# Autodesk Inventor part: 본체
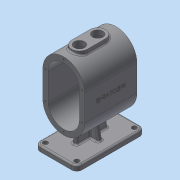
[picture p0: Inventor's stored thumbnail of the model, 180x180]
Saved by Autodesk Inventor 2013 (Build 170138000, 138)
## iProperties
Created: 2016-12
Part Number: 본체
Material: 알루미늄 6061
Document SubType Name: Modeling
Designer: mduedu
Density: 1 g/cm^3
Mass: 432.112 g
Surface Area: 1014.94 cm^2
Volume: 432.112 cm^3
Author: mduedu
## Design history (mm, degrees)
sketch "스케치1"
  geometry: L1 (40, -25)-(40, 25); L2 (-40, 25)-(-40, -25); L3 (-40, -25)-(40, 25); L4 (40, -25)-(-40, 25); L5 (0, 25)-(0, -25); A1 r 40 centre (0, 25) between (40, 25) and (-40, 25); A2 r 40 centre (0, -25) between (-40, -25) and (40, -25); 1 further point
  constraints: 10 end point, 4 point on circle, 3 tangent, 2 centre point, 2 midpoint, 2 parallel, 1 vertical
  dimensions: "d0" = 130 dimension on A2 A1; "d2" = 80 distance between parallel lines of L1 L2
extrude "돌출1" new body sketch "스케치1" stored distance "d3" = 100; taper "d4" = 0 deg
feature "쉘1" dims "d5" = 10
sketch "스케치2"
  geometry: L1 (-90, 65)-(-100, 65); L2 (-100, 65)-(-100, -65); L3 (-100, -65)-(-90, -65); L4 (-90, -65)-(-90, 65); 2 further points
  constraints: 8 end point, 2 parallel, 1 horizontal, 1 horizontal alignment, 1 midpoint, 1 perpendicular
  dimensions: "d6" = 100 distance from line of L2 point (0, 0); "d7" = 130 distance of L1.end L2.end; "d8" = 10 distance of L2.end L3.end
extrude "돌출2" join sketch "스케치2" stored distance "d9" = 80; taper "d10" = 0 deg
fillet "모깎기1" dims "d11" = 10
sketch "스케치3"
  geometry: L1 (-10, 10)-(-10, 120) reference; L2 (60, 0)-(0, 0) reference; L3 (70, 120)-(70, 10) reference; L4 (0, 130)-(60, 130) reference; A1 r 10 centre (0, 120) between (0, 130) and (-10, 120) reference; A2 r 10 centre (0, 10) between (-10, 10) and (0, 0) reference; A3 r 10 centre (60, 10) between (60, 0) and (70, 10) reference; A4 r 10 centre (60, 120) between (70, 120) and (60, 130) reference; 5 further points
  constraints: 4 coincident
hole "구멍1" sketch "스케치3" at (60, 120), (60, 10), (0, 10), (0, 120) diameter "d12" = 9; stored, may be unused: countersink angle "d16" = 90 deg, drill point angle "d18" = 118 deg; dims "d13" = 6, "d14" = 4, "d15" = 2, "d17" = 8
sketch "스케치5"
  geometry: L1 (34, 35)-(26, 35); L2 (26, 35)-(26, 95); L3 (26, 95)-(34, 95); L4 (34, 95)-(34, 35); L5 (34, 35)-(26, 95); L6 (26, 35)-(34, 95); 1 further point
  constraints: 12 end point, 2 midpoint, 2 parallel, 1 horizontal, 1 perpendicular
  dimensions: "d22" = 8 distance of L2.end L3.end; "d24" = 60 distance of L1.end L2.end
extrude "돌출3" join sketch "스케치5" stored distance "d25" = 80; taper "d26" = 0 deg
feature "면 기울기1" dims angle "d27" = 5 deg
sketch "스케치6"
  geometry: L1 (-30, -90)-(30, -90) reference; L2 (-15.072, -62.052)-(-20, -90); A1 r 40 centre (0, -25) between (-40, -25) and (40, -25) reference; 1 further point
  constraints: 2 end point, 1 point on circle, 1 point on line
  dimensions: "d28" = 20 horizontal distance of A1.centre L2.end; "d29" = 80 deg angle of L2 L1
feature "리브1" sketch "스케치6" dims "d30" = 1, "d31" = 8, "d32" = 0, "d33" = 0, "d34" = 1, "d35" = 1
fillet "모깎기2" dims "d36" = 3
fillet "모깎기3" dims "d37" = 3, "d38" = 3
node "작업 평면1"
sketch "스케치9"
  geometry: 1 further point
sketch "스케치7"
  geometry: L1 (40, 50)-(-40, 50) reference; C1 r 15 at (0, 20); 1 further point
  constraints: 1 centre point, 1 vertical alignment
  dimensions: "d40" = 30 diameter of C1; "d41" = 30 distance from line of C1.centre L1
extrude "돌출4" join sketch "스케치7" stored distance "d42" = 80; taper "d43" = 0 deg
sketch "스케치15"
  geometry: C1 r 15 at (0, -15); C2 r 15 at (0, 20) reference; 1 further point
  constraints: 1 centre point, 1 vertical alignment
  dimensions: "d83" = 30 diameter of C1; "d84" = 35 distance of C1.centre C2.centre
extrude "돌출6" join sketch "스케치15" stored distance "d85" = 10; taper "d86" = 0 deg
hole "구멍2" diameter "d46" = 20; stored, may be unused: countersink angle "d50" = 90 deg, drill point angle "d52" = 118 deg; dims "d44" = 10, "d45" = 10, "d47" = 6, "d48" = 4, "d49" = 2, "d51" = 8
hole "구멍6" diameter "d89" = 20; stored, may be unused: countersink angle "d93" = 90 deg, drill point angle "d95" = 118 deg; dims "d87" = 10, "d88" = 10, "d90" = 6, "d91" = 4, "d92" = 2, "d94" = 8
node "작업 평면2"
sketch "스케치8"
  geometry: C1 r 15 at (0, 0) reference; C2 r 15 at (0, 0); 1 further point
  constraints: 1 centre point, 1 coincident
  dimensions: "d55" = 30 diameter of C2
extrude "돌출5" cut sketch "스케치8" stored distance "d56" = 80; taper "d57" = 0 deg
sketch "스케치16"
  geometry: C1 r 15 at (0, 35); 2 further points
  constraints: 1 centre point, 1 coincident, 1 vertical alignment
  dimensions: "d96" = 30 diameter of C1
extrude "돌출7" cut sketch "스케치16" stored distance "d97" = 10; taper "d98" = 0 deg
sketch "스케치17"
  geometry: L1 (15, 0)-(15, -35); L2 (-15, 0)-(-15, -35); C1 r 10 at (0, 0) reference; C2 r 10 at (0, -35) reference; A1 r 15 centre (0, 0) between (15, 0) and (-15, 0) reference; A2 r 15 centre (0, -35) between (15, -35) and (-15, -35) reference; 1 further point
  constraints: 4 end point, 4 point on circle, 3 tangent, 1 vertical
extrude "돌출8" join sketch "스케치17" stored distance "d99" = 10; taper "d100" = 0 deg
fillet "모깎기5" dims "d101" = 3
chamfer "모따기1" distance "d58" = 1; stored, may be unused: second distance "d59" = 2, angle "d60" = 45 deg
sketch "스케치10"
  geometry: 2 further points
  constraints: 1 coincident, 1 other
feature "엠보싱1" sketch "스케치10" dims "d0" = 130, "d2" = 80, "d11" = 10, "d61" = 0.5, "d62" = 0
sketch "스케치11"
  geometry: 1 further point
hole "구멍3" sketch "스케치11" at (0, 60) diameter "d63" = 3.242; stored, may be unused: countersink angle "d67" = 90 deg, drill point angle "d69" = 120 deg; dims "d64" = 8.6, "d65" = 4, "d66" = 2, "d68" = 10.6
sketch "스케치12"
  geometry: 1 further point
hole "구멍5" sketch "스케치12" at (0, 60) diameter "d70" = 3.242; stored, may be unused: countersink angle "d74" = 90 deg, drill point angle "d76" = 120 deg; dims "d71" = 8.6, "d72" = 4, "d73" = 2, "d75" = 10.6
node "솔리드1"
mirror "대칭1"
pattern_linear "직사각형 패턴1"
pattern_linear "직사각형 패턴2"
node "투영된 루프1"
sketch "스케치13"
  geometry: L1 (-40, 25)-(-40, -25) reference; L2 (40, -25)-(40, 25) reference; L3 (35, 25)-(35, -25); L4 (-35, -25)-(-35, 25); A1 r 40 centre (0, 25) between (40, 25) and (-40, 25) reference; A2 r 40 centre (0, -25) between (-40, -25) and (40, -25) reference; A3 r 35 centre (0, 25) between (35, 25) and (-35, 25); A4 r 35 centre (0, -25) between (-35, -25) and (35, -25); 2 further points
  constraints: 5 point on circle, 4 end point, 2 centre point, 3 other
  dimensions: "d77" = 5 distance between parallel lines of L3 L2
sketch "스케치14"
  geometry: L1 (-40, 25)-(-40, -25) reference; L2 (40, -25)-(40, 25) reference; L3 (35, 25)-(35, -25); L4 (-35, -25)-(-35, 25); A1 r 40 centre (0, 25) between (40, 25) and (-40, 25) reference; A2 r 40 centre (0, -25) between (-40, -25) and (40, -25) reference; A3 r 35 centre (0, 25) between (35, 25) and (-35, 25); A4 r 35 centre (0, -25) between (-35, -25) and (35, -25); 2 further points
  constraints: 5 point on circle, 4 end point, 2 centre point, 3 other
  dimensions: "d80" = 5 distance between parallel lines of L2 L3
node "투영된 루프3"
node "투영된 루프4"
node "투영된 루프5"
